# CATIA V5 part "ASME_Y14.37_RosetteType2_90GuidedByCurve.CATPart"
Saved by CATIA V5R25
Part number: AP242_ASMEY14.37_TypeII-Rosette-90GuidedByCurve
Bounding box of the stored display mesh (mm): x -8980.256 to 8980.256, y -8980.236 to 8980.236, z 8980.256 to 12700.457
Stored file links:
  C:\Users\jvl2147\Documents\ASME Y14.37\ASME_Y14.37_RosetteType2_90GuidedByCurve.CATPart
  \\Nw\787lib\787-PROCINT-WKG\Dom_SSDBS\DM\!!ShareFileForWritingServices\Composites\Standards and References\ASME Y14.37\ASME-Y14.37_COMPOSITES-A.CATMaterial
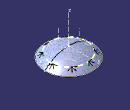
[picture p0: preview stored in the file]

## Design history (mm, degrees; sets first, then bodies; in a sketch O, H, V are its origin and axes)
CompParametersFeature1 "CATCoParametersFeatName": Value 0, Value 45, Value 0, Value 45, Value -45, Value 90, default 0
CompStacking1 "Stacking"
CompEOPGroupFeature1 "CATCoEOPGroupFeatName"
AxisSystem1 "Local Part Axis": origin (0, 0, 12700), X (1, 0, 0), Y (0, 1, 0), Z (0, 0, 1)
Set1 "Construction Geometry (REF)"
  Set2 "Surface Construction"
    Point1: (0, 0, 0)
    Plane1: type 1Curve, Element1 edge of Sphere1
    Plane2: type Offset, RefPlane Plane1, Offset 25.4
  Set3 "Rosette Construction"
    Plane3: type 1Line1Pt, RefPoint Point4, Line edge [ZX plane of AxisSystem1 | YZ plane of AxisSystem1]
    Line1: type Normal, RefPoint Point4, RefSkin Plane3, Start 0, End 2540
    Line2: type Normal, RefPoint Point4, RefSkin Sphere1, Start 0, End 2540
    Plane4: type 2Lines, Element1 Line1, Element2 Line2
    Line3: type Normal, RefPoint Point4, RefSkin Plane4, Start 0, End 2565.4
    Point2: type OnCurve, Support Line3, Length 457.2
    Line4: type Angle, RefPoint Point2, Curve Line3, Support XY plane of AxisSystem9, Start -203.2, End 203.2, Angle 90
    Project1 "Part Center": ToProject Point1, Support Sphere1, Direction xy-plane
  Set4 "Transferred Rosettes Construction"
    Set5 "TransferredRosette1"
      Plane5: type 1Line1Pt, RefPoint Point3, Line edge [ZX plane of AxisSystem1 | YZ plane of AxisSystem1]
      Line5: type Normal, RefPoint Point3, RefSkin Plane5, Start 0, End 2540
      Line6: type Normal, RefPoint Point3, RefSkin Sphere1, Start 0, End 2540
      Plane6: type 2Lines, Element1 Line5, Element2 Line6
      Line7: type Normal, RefPoint Point3, RefSkin Plane6, Start 0, End 2565.4
      Point3: type OnCurve, Support Intersect2, RefPoint Point4, Length 5080, Direction Plane3
      AxisSystem2: origin (5121.3475, -4577.7153, 10682.0561), X (0.6271, -0.5605, -0.5409), Y (0.6664, 0.7456, 0), Z (0.4033, -0.3605, 0.8411)
    PointsRepetition1: FirstPoint Point3, Curve Intersect2, SecondPoint Point4
    Set6 "TransferredRosette2"
      Plane7: type 1Line1Pt, RefPoint {point type OnCurve, RefPoint Point3, Support Intersect2, Length 37338 {= PointsRepetition1.Length * 7}}, Line edge [ZX plane of AxisSystem1 | YZ plane of AxisSystem1]
      Line8: type Normal, RefPoint {point type OnCurve, RefPoint Point3, Support Intersect2, Length 37338 {= PointsRepetition1.Length * 7}}, RefSkin Plane7, Start 0, End 2540
      Line9: type Normal, RefPoint {point type OnCurve, RefPoint Point3, Support Intersect2, Length 37338 {= PointsRepetition1.Length * 7}}, RefSkin Sphere1, Start 0, End 2540
      Plane8: type 2Lines, Element1 Line8, Element2 Line9
      Line10: type Normal, RefPoint {point type OnCurve, RefPoint Point3, Support Intersect2, Length 37338 {= PointsRepetition1.Length * 7}}, RefSkin Plane10, Start 0, End 2565.4
      AxisSystem3: origin (6821.204, 809.2297, 10682.0561), X (0.8352, 0.0991, -0.5409), Y (-0.1178, 0.993, 0), Z (0.5371, 0.0637, 0.8411)
    Set7 "TransferredRosette3"
      Plane9: type 1Line1Pt, RefPoint {point type OnCurve, Support Intersect2, RefPoint Point3, Length 32004 {= PointsRepetition1.Length * 6}}, Line edge [ZX plane of AxisSystem1 | YZ plane of AxisSystem1]
      Line11: type Normal, RefPoint {point type OnCurve, Support Intersect2, RefPoint Point3, Length 32004 {= PointsRepetition1.Length * 6}}, RefSkin Plane9, Start 0, End 2540
      Line12: type Normal, RefPoint {point type OnCurve, Support Intersect2, RefPoint Point3, Length 32004 {= PointsRepetition1.Length * 6}}, RefSkin Sphere1, Start 0, End 2540
      Plane10: type 2Lines, Element1 Line11, Element2 Line12
      Line13: type Normal, RefPoint {point type OnCurve, Support Intersect2, RefPoint Point3, Length 32004 {= PointsRepetition1.Length * 6}}, RefSkin Plane10, Start 0, End 2565.4
      AxisSystem4: origin (4298.7992, 5357.6116, 10682.0561), X (0.5264, 0.656, -0.5409), Y (-0.78, 0.6258, 0), Z (0.3385, 0.4219, 0.8411)
    Set8 "TransferredRosette4"
      Plane11: type 1Line1Pt, RefPoint {point type OnCurve, Support Intersect2, RefPoint Point3, Length 26670 {= PointsRepetition1.Length * 5}}, Line edge [ZX plane of AxisSystem1 | YZ plane of AxisSystem1]
      Line14: type Normal, RefPoint {point type OnCurve, Support Intersect2, RefPoint Point3, Length 26670 {= PointsRepetition1.Length * 5}}, RefSkin Plane11, Start 0, End 2540
      Line15: type Normal, RefPoint {point type OnCurve, Support Intersect2, RefPoint Point3, Length 26670 {= PointsRepetition1.Length * 5}}, RefSkin Sphere1, Start 0, End 2540
      Plane12: type 2Lines, Element1 Line14, Element2 Line15
      Line16: type Normal, RefPoint {point type OnCurve, Support Intersect2, RefPoint Point3, Length 26670 {= PointsRepetition1.Length * 5}}, RefSkin Plane12, Start 0, End 2565.4
      AxisSystem5: origin (-688.0983, 6834.4859, 10682.0561), X (-0.0843, 0.8369, -0.5409), Y (-0.995, -0.1002, 0), Z (-0.0542, 0.5381, 0.8411)
    Set9 "TransferredRosette5"
      Plane13: type 1Line1Pt, RefPoint {point type OnCurve, Support Intersect2, RefPoint Point3, Length 21336 {= PointsRepetition1.Length * 4}}, Line edge [ZX plane of AxisSystem1 | YZ plane of AxisSystem1]
      Line17: type Normal, RefPoint {point type OnCurve, Support Intersect2, RefPoint Point3, Length 21336 {= PointsRepetition1.Length * 4}}, RefSkin Plane13, Start 0, End 2540
      Line18: type Normal, RefPoint {point type OnCurve, Support Intersect2, RefPoint Point3, Length 21336 {= PointsRepetition1.Length * 4}}, RefSkin Sphere1, Start 0, End 2540
      Plane14: type 2Lines, Element1 Line17, Element2 Line18
      Line19: type Normal, RefPoint {point type OnCurve, Support Intersect2, RefPoint Point3, Length 21336 {= PointsRepetition1.Length * 4}}, RefSkin Plane14, Start 0, End 2565.4
      AxisSystem6: origin (-5280.5105, 4393.1635, 10682.0561), X (-0.6466, 0.5379, -0.5409), Y (-0.6396, -0.7687, 0), Z (-0.4158, 0.3459, 0.8411)
    Set10 "TransferredRosette6"
      Plane15: type 1Line1Pt, RefPoint {point type OnCurve, Support Intersect2, RefPoint Point3, Length 16002 {= PointsRepetition1.Length * 3}}, Line edge [ZX plane of AxisSystem1 | YZ plane of AxisSystem1]
      Line20: type Normal, RefPoint {point type OnCurve, Support Intersect2, RefPoint Point3, Length 16002 {= PointsRepetition1.Length * 3}}, RefSkin Plane15, Start 0, End 2540
      Line21: type Normal, RefPoint {point type OnCurve, Support Intersect2, RefPoint Point3, Length 16002 {= PointsRepetition1.Length * 3}}, RefSkin Sphere1, Start 0, End 2540
      Plane16: type 2Lines, Element1 Line20, Element2 Line21
      Line22: type Normal, RefPoint {point type OnCurve, Support Intersect2, RefPoint Point3, Length 16002 {= PointsRepetition1.Length * 3}}, RefSkin Plane16, Start 0, End 2565.4
      AxisSystem7: origin (-6845.6169, -566.7504, 10682.0561), X (-0.8382, -0.0694, -0.5409), Y (0.0825, -0.9966, 0), Z (-0.539, -0.0446, 0.8411)
    Set11 "TransferredRosette7"
      Plane17: type 1Line1Pt, RefPoint {point type OnCurve, Support Intersect2, RefPoint Point3, Length 10668 {= PointsRepetition1.Length * 2}}, Line edge [ZX plane of AxisSystem1 | YZ plane of AxisSystem1]
      Line23: type Normal, RefPoint {point type OnCurve, Support Intersect2, RefPoint Point3, Length 10668 {= PointsRepetition1.Length * 2}}, RefSkin Plane17, Start 0, End 2540
      Line24: type Normal, RefPoint {point type OnCurve, Support Intersect2, RefPoint Point3, Length 10668 {= PointsRepetition1.Length * 2}}, RefSkin Sphere1, Start 0, End 2540
      Plane18: type 2Lines, Element1 Line23, Element2 Line24
      Line25: type Normal, RefPoint {point type OnCurve, Support Intersect2, RefPoint Point3, Length 10668 {= PointsRepetition1.Length * 2}}, RefSkin Plane18, Start 0, End 2565.4
      AxisSystem8: origin (-4486.1453, -5201.7475, 10682.0561), X (-0.5493, -0.6369, -0.5409), Y (0.7573, -0.6531, 0), Z (-0.3532, -0.4096, 0.8411)
Set12 "Engineering Geometry"
  Set13 "Engineering Surface"
    Sphere1 "Definition Surface - Dome": Center Point1, Radius 12700, Angle1 45, Angle3 0, Angle4 360
  Set14 "Engineering Edge of Part"
    Intersect1 "EEOP": ToIntersect1 Plane2, ToIntersect2 Sphere1
  Set15 "Engineering Rosette"
    Intersect2 "Guide_Curve_90_Rosette1": ToIntersect1 {plane type Offset, RefPlane Plane2, Offset 1676.4}, ToIntersect2 Sphere1
    Point4 "Rosette Origin": type OnCurve, Support Intersect2, RefPoint {extremum Reference Intersect1, Direction (1, 2, 3)}, Ratio 1.41
    AxisSystem9 "Axis System - Rosette": origin (698.3279, -6833.4483, 10682.0561), X (0.0855, -0.8367, -0.5409), Y (0.9948, 0.1017, 0), Z (0.055, -0.5381, 0.8411)
Body1 "ASMEY14.37_TypeII-Rosette-90GuidedByCurve" (main body)
  Solid1: solid without history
